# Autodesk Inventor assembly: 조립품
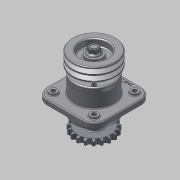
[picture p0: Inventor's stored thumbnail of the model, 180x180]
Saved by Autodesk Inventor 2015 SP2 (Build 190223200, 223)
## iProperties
Created: 2015-07
Part Number: 조립품
Document SubType Name: Assembly
Designer: AMC
Author: AMC
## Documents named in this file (12)
- C:\Users\AMC\Desktop\450735V1005\조립품.iam
- C:\Users\AMC\Desktop\450735V1005\본체.ipt
- C:\Users\AMC\Desktop\450735V1005\2-커버.ipt
- C:\Users\AMC\Desktop\450735V1005\3-축.ipt
- C:\Users\AMC\Desktop\450735V1005\4-V벨트풀리.ipt
- C:\Users\AMC\Desktop\450735V1005\5-체인 스프로킷.ipt
- C:\Users\AMC\Desktop\450735V1005\6-베어링 6206.ipt
- C:\Users\AMC\Desktop\450735V1005\7-부시.ipt
- C:\Users\AMC\Desktop\450735V1005\8-오일실 30x42.ipt
- C:\Users\AMC\Desktop\450735V1005\9-M16-너트.ipt
- C:\Users\AMC\Desktop\450735V1005\10-M6.ipt
- C:\Users\AMC\Desktop\450735V1005\11-키 6x6.ipt
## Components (22 placed, 10 different names)
1. 2-커버:1
2. 3-축:1
3. 4-V벨트풀리:1
4. 5-체인 스프로킷:1
5. 6-베어링 6206:1
6. 7-부시:1
7. 8-8-오일실 30x42:1
8. 9-M16 너트:1
9. 10-M6:1
10. 11-키 6x6:1
11. 6-베어링 6206:2
12. 2-커버:2
13. 8-8-오일실 30x42:2
14. 10-M6:2
15. 10-M6:3
16. 10-M6:4
17. 10-M6:7
18. 10-M6:8
19. 10-M6:9
20. 10-M6:10
21. 11-키 6x6:2
22. 9-M16 너트:2
